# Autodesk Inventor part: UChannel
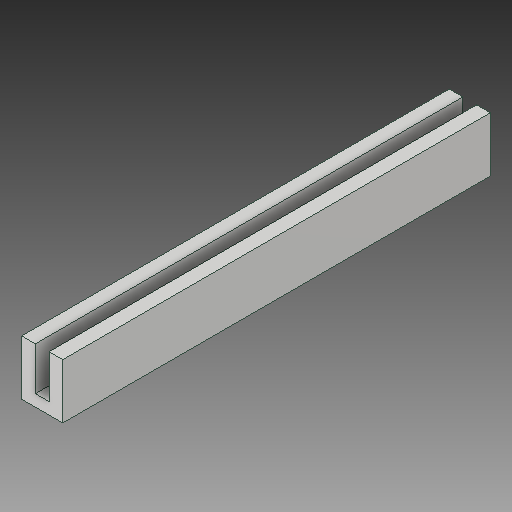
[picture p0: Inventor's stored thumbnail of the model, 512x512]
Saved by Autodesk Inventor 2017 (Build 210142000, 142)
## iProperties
Created: 2017-05
Part Number: UChannel
Material: Generic
Document SubType Name: Modeling
Designer: Savy
Density: 1 g/cm^3
Appearance: Default
Mass: 8.83789 g
Surface Area: 65.6285 cm^2
Volume: 8.83789 cm^3
Author: Savy
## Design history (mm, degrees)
feature "SOLID1"
body "Solid1"
